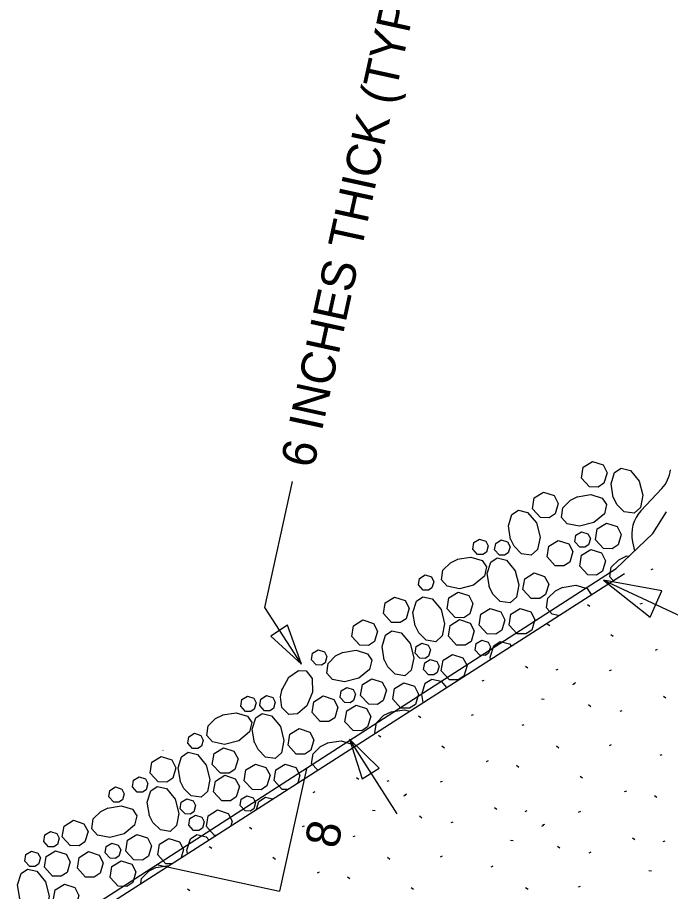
# Model space of a CAD drawing. Extents: x 2126110 to 2128246, y 1804858 to 1811658.
# Drawn here: x 2126563.9 to 2126659.7, y 1805428.3 to 1805556.7 of the extents above; entities that cross this region are included whole.
import ezdxf

# ---------------------------------------------------------------- set-up
doc = ezdxf.new("R2010")
doc.units = 0
doc.layers.add('1', color=7, linetype='Continuous')

msp = doc.modelspace()

# ---------------------------------------------------------------- linework, layer by layer
at = {"layer": '1'}
for p, q in [((2126600.2, 1805470.02), (2126604.25, 1805488.54)), ((2126653.13, 1805477.56), (2126653.52, 1805477.63)), ((2126573.8, 1805425.5), (2126651.74, 1805475.78)), ((2126574.76, 1805424.89), (2126652.95, 1805475.05)), ((2126656.88, 1805475.6), (2126657.18, 1805475.71)), ((2126649.91, 1805474.04), (2126706.07, 1805447.86)), ((2126605.54, 1805461.7), (2126600.2, 1805470.02)), ((2126647.89, 1805470.19), (2126647.53, 1805470.45)), ((2126655.29, 1805470.57), (2126655.59, 1805470.69)), ((2126641.99, 1805467.34), (2126641.64, 1805467.6)), ((2126651.33, 1805465.76), (2126650.98, 1805466.02)), ((2126657.53, 1805463.8), (2126657.83, 1805463.92)), ((2126638.77, 1805461.14), (2126638.42, 1805461.4)), ((2126642.93, 1805460.89), (2126643.23, 1805461.01)), ((2126650.78, 1805460.79), (2126651.08, 1805460.91)), ((2126632.08, 1805459.25), (2126632.38, 1805459.36)), ((2126645.38, 1805458.74), (2126645.68, 1805458.86)), ((2126645.52, 1805458.89), (2126645.82, 1805459.01)), ((2126659.04, 1805456.71), (2126658.68, 1805456.97)), ((2126640.79, 1805456.64), (2126641.19, 1805456.6)), ((2126648.04, 1805455.48), (2126647.69, 1805455.74)), ((2126630.49, 1805454.22), (2126630.79, 1805454.34)), ((2126652.34, 1805454.82), (2126652.64, 1805454.94)), ((2126623.08, 1805453.84), (2126622.73, 1805454.1)), ((2126637.93, 1805452.77), (2126638.22, 1805452.88)), ((2126619.62, 1805439.77), (2126612.6, 1805450.7)), ((2126617.19, 1805450.99), (2126616.84, 1805451.25)), ((2126626.53, 1805449.41), (2126626.18, 1805449.67)), ((2126643.35, 1805449.41), (2126642.99, 1805449.67)), ((2126650.75, 1805449.79), (2126651.05, 1805449.91)), ((2126585.26, 1805449.04), (2126585.23, 1805449.07)), ((2126658.19, 1805448.34), (2126658.49, 1805448.46)), ((2126632.73, 1805447.45), (2126633.03, 1805447.56)), ((2126637.45, 1805446.57), (2126637.1, 1805446.82)), ((2126606.27, 1805446.33), (2126602.35, 1805428.37)), ((2126613.97, 1805444.79), (2126613.62, 1805445.05)), ((2126618.13, 1805444.54), (2126618.42, 1805444.66)), ((2126625.97, 1805444.44), (2126626.27, 1805444.56)), ((2126646.79, 1805444.98), (2126646.44, 1805445.24)), ((2126603.48, 1805443.32), (2126602.74, 1805443.33)), ((2126607.28, 1805442.9), (2126607.57, 1805443.01)), ((2126652.99, 1805443.02), (2126653.29, 1805443.14)), ((2126620.58, 1805442.39), (2126620.88, 1805442.51)), ((2126620.72, 1805442.54), (2126621.02, 1805442.66)), ((2126657.71, 1805442.14), (2126657.36, 1805442.4)), ((2126615.99, 1805440.29), (2126616.39, 1805440.25)), ((2126634.23, 1805440.36), (2126633.88, 1805440.62)), ((2126638.39, 1805440.11), (2126638.69, 1805440.23)), ((2126623.24, 1805439.13), (2126622.88, 1805439.39)), ((2126646.24, 1805440.01), (2126646.54, 1805440.13)), ((2126598.28, 1805437.49), (2126597.93, 1805437.75)), ((2126605.69, 1805437.87), (2126605.98, 1805437.99)), ((2126627.54, 1805438.47), (2126627.84, 1805438.58)), ((2126640.84, 1805437.96), (2126641.14, 1805438.08)), ((2126640.98, 1805438.11), (2126641.28, 1805438.23)), ((2126592.98, 1805436.58), (2126592.8, 1805436.58)), ((2126613.12, 1805436.42), (2126613.42, 1805436.53)), ((2126636.25, 1805435.86), (2126636.65, 1805435.82)), ((2126654.5, 1805435.93), (2126654.14, 1805436.19)), ((2126658.65, 1805435.69), (2126658.95, 1805435.8)), ((2126592.39, 1805434.64), (2126592.03, 1805434.9)), ((2126643.5, 1805434.7), (2126643.15, 1805434.96)), ((2126647.8, 1805434.04), (2126648.1, 1805434.16)), ((2126601.73, 1805433.06), (2126601.37, 1805433.32)), ((2126618.54, 1805433.06), (2126618.19, 1805433.32)), ((2126625.95, 1805433.44), (2126626.25, 1805433.56)), ((2126584.18, 1805431.86), (2126586.12, 1805432.18)), ((2126584.3, 1805432.32), (2126602.35, 1805428.37)), ((2126586.46, 1805432.4), (2126585.66, 1805432.42)), ((2126607.93, 1805431.1), (2126608.22, 1805431.21)), ((2126633.39, 1805431.99), (2126633.68, 1805432.11)), ((2126656.52, 1805431.43), (2126656.92, 1805431.39)), ((2126612.65, 1805430.21), (2126612.3, 1805430.47)), ((2126589.17, 1805428.44), (2126588.81, 1805428.7)), ((2126621.99, 1805428.63), (2126621.64, 1805428.89)), ((2126638.81, 1805428.63), (2126638.45, 1805428.89)), ((2126646.21, 1805429.02), (2126646.51, 1805429.13))]:
    msp.add_line(p, q, dxfattribs=at)
for points in [[(2126647.82, 1805487.76), (2126646.64, 1805489.05), (2126646.89, 1805490.64), (2126648.26, 1805491.49), (2126649.82, 1805490.98), (2126650.41, 1805489.83), (2126649.96, 1805488.3), (2126649.09, 1805487.73), (2126647.82, 1805487.76)], [(2126651.33, 1805486.19), (2126651, 1805488.19), (2126651.52, 1805489.86), (2126652.46, 1805490.49), (2126653.83, 1805490.17), (2126655.12, 1805488.61), (2126655.65, 1805486.51), (2126655.3, 1805484.73), (2126654.37, 1805483.88), (2126652.93, 1805484.1), (2126651.84, 1805485.18), (2126651.3, 1805486.28)], [(2126640.66, 1805483.25), (2126639.47, 1805484.54), (2126639.72, 1805486.13), (2126641.1, 1805486.98), (2126642.65, 1805486.48), (2126643.25, 1805485.33), (2126642.79, 1805483.8), (2126641.93, 1805483.22), (2126640.66, 1805483.25)], [(2126646.04, 1805486.29), (2126648.04, 1805486.62), (2126649.7, 1805486.1), (2126650.34, 1805485.16), (2126650.02, 1805483.79), (2126648.45, 1805482.5), (2126646.36, 1805481.97), (2126644.57, 1805482.33), (2126643.73, 1805483.26), (2126643.94, 1805484.69), (2126645.03, 1805485.78), (2126646.13, 1805486.32)], [(2126655.38, 1805484.22), (2126658.45, 1805487.53)], [(2126636.26, 1805480.04), (2126635.93, 1805482.04), (2126636.45, 1805483.7), (2126637.39, 1805484.34), (2126638.75, 1805484.01), (2126640.05, 1805482.45), (2126640.58, 1805480.36), (2126640.22, 1805478.57), (2126639.29, 1805477.73), (2126637.86, 1805477.94), (2126636.77, 1805479.03), (2126636.23, 1805480.12)], [(2126651.74, 1805475.78), (2126657.13, 1805480.92), (2126659.15, 1805484.08)], [(2126649.9, 1805478.68), (2126648.71, 1805479.98), (2126648.97, 1805481.57), (2126650.34, 1805482.41), (2126651.89, 1805481.91), (2126652.49, 1805480.76), (2126652.04, 1805479.23), (2126651.17, 1805478.66), (2126649.9, 1805478.69)], [(2126631.41, 1805477.83), (2126630.7, 1805478.61), (2126630.85, 1805479.56), (2126631.67, 1805480.07), (2126632.61, 1805479.77), (2126632.96, 1805479.08), (2126632.69, 1805478.16), (2126632.17, 1805477.82), (2126631.41, 1805477.83)], [(2126646.4, 1805478.92), (2126645.69, 1805479.7), (2126645.84, 1805480.65), (2126646.67, 1805481.16), (2126647.6, 1805480.86), (2126647.96, 1805480.17), (2126647.69, 1805479.25), (2126647.16, 1805478.91), (2126646.4, 1805478.92)], [(2126634.62, 1805477.72), (2126633.91, 1805478.5), (2126634.06, 1805479.45), (2126634.88, 1805479.96), (2126635.82, 1805479.66), (2126636.17, 1805478.97), (2126635.9, 1805478.05), (2126635.38, 1805477.7), (2126634.62, 1805477.72)], [(2126642.79, 1805476.16), (2126641.61, 1805477.46), (2126641.86, 1805479.05), (2126643.23, 1805479.89), (2126644.79, 1805479.39), (2126645.38, 1805478.24), (2126644.93, 1805476.71), (2126644.06, 1805476.14), (2126642.79, 1805476.17)], [(2126654.47, 1805478.38), (2126654.17, 1805479.7)], [(2126628.42, 1805477.12), (2126630.42, 1805477.45), (2126632.09, 1805476.93), (2126632.72, 1805475.99), (2126632.4, 1805474.62), (2126630.83, 1805473.33), (2126628.74, 1805472.8), (2126626.96, 1805473.15), (2126626.11, 1805474.08), (2126626.32, 1805475.52), (2126627.41, 1805476.61), (2126628.51, 1805477.15)], [(2126647.6, 1805474.83), (2126646.41, 1805476.12), (2126646.67, 1805477.71), (2126648.04, 1805478.56), (2126649.59, 1805478.05), (2126650.19, 1805476.9), (2126649.74, 1805475.37), (2126648.87, 1805474.8), (2126647.6, 1805474.83)], [(2126651.3, 1805473.99), (2126650.81, 1805474.53), (2126651.03, 1805475.96), (2126652.12, 1805477.05), (2126653.21, 1805477.59)], [(2126633.14, 1805473.03), (2126632.81, 1805475.03), (2126633.33, 1805476.69), (2126634.27, 1805477.33), (2126635.64, 1805477), (2126636.93, 1805475.44), (2126637.46, 1805473.35), (2126637.11, 1805471.56), (2126636.18, 1805470.72), (2126634.74, 1805470.93), (2126633.65, 1805472.02), (2126633.11, 1805473.11)], [(2126639.25, 1805471.38), (2126638.06, 1805472.67), (2126638.32, 1805474.26), (2126639.69, 1805475.11), (2126641.24, 1805474.6), (2126641.84, 1805473.46), (2126641.39, 1805471.93), (2126640.52, 1805471.35), (2126639.25, 1805471.38)], [(2126623.43, 1805472.58), (2126622.72, 1805473.36), (2126622.87, 1805474.31), (2126623.69, 1805474.82), (2126624.63, 1805474.52), (2126624.98, 1805473.83), (2126624.71, 1805472.91), (2126624.19, 1805472.57), (2126623.43, 1805472.58)], [(2126628.13, 1805468.57), (2126626.94, 1805469.86), (2126627.19, 1805471.46), (2126628.57, 1805472.3), (2126630.12, 1805471.8), (2126630.72, 1805470.65), (2126630.27, 1805469.12), (2126629.4, 1805468.54), (2126628.13, 1805468.57)], [(2126643.3, 1805468.85), (2126642.36, 1805469.04), (2126641.51, 1805469.97), (2126641.73, 1805471.41), (2126642.82, 1805472.5), (2126643.91, 1805473.04)], [(2126643.82, 1805473), (2126645.83, 1805473.33), (2126647.49, 1805472.82), (2126648.09, 1805471.93)], [(2126618.78, 1805467.85), (2126617.59, 1805469.14), (2126617.85, 1805470.74), (2126619.22, 1805471.58), (2126620.78, 1805471.08), (2126621.37, 1805469.93), (2126620.92, 1805468.4), (2126620.05, 1805467.82), (2126618.78, 1805467.85)], [(2126622.25, 1805467.33), (2126621.92, 1805469.33), (2126622.44, 1805470.99), (2126623.38, 1805471.63), (2126624.75, 1805471.3), (2126626.04, 1805469.74), (2126626.57, 1805467.65), (2126626.22, 1805465.86), (2126625.29, 1805465.01), (2126623.85, 1805465.23), (2126622.76, 1805466.32), (2126622.22, 1805467.41)], [(2126632.82, 1805466.17), (2126631.63, 1805467.46), (2126631.88, 1805469.06), (2126633.26, 1805469.9), (2126634.81, 1805469.4), (2126635.41, 1805468.25), (2126634.95, 1805466.72), (2126634.09, 1805466.14), (2126632.82, 1805466.17)], [(2126637.21, 1805466.18), (2126636.03, 1805467.47), (2126636.28, 1805469.07), (2126637.65, 1805469.91), (2126639.21, 1805469.41), (2126639.8, 1805468.26), (2126639.35, 1805466.73), (2126638.48, 1805466.15), (2126637.21, 1805466.18)], [(2126614.13, 1805464.49), (2126612.94, 1805465.78), (2126613.19, 1805467.37), (2126614.57, 1805468.22), (2126616.12, 1805467.71), (2126616.72, 1805466.56), (2126616.26, 1805465.04), (2126615.4, 1805464.46), (2126614.13, 1805464.49)], [(2126628.32, 1805464.53), (2126627.13, 1805465.82), (2126627.39, 1805467.41), (2126628.76, 1805468.26), (2126630.31, 1805467.75), (2126630.91, 1805466.6), (2126630.46, 1805465.07), (2126629.59, 1805464.5), (2126628.32, 1805464.53)], [(2126617.71, 1805462.33), (2126617.38, 1805464.33), (2126617.9, 1805465.99), (2126618.84, 1805466.63), (2126620.21, 1805466.3), (2126621.5, 1805464.74), (2126622.03, 1805462.65), (2126621.67, 1805460.86), (2126620.74, 1805460.02), (2126619.31, 1805460.23), (2126618.22, 1805461.32), (2126617.68, 1805462.41)], [(2126622.94, 1805462.58), (2126622.22, 1805463.35), (2126622.38, 1805464.31), (2126623.2, 1805464.81), (2126624.13, 1805464.51), (2126624.49, 1805463.82), (2126624.22, 1805462.9), (2126623.7, 1805462.56), (2126622.94, 1805462.58)], [(2126631.75, 1805463.02), (2126631.04, 1805463.8), (2126631.19, 1805464.75), (2126632.01, 1805465.26), (2126632.94, 1805464.96), (2126633.3, 1805464.27), (2126633.03, 1805463.35), (2126632.51, 1805463), (2126631.75, 1805463.02)], [(2126633.32, 1805462.45), (2126633.27, 1805462.73), (2126633.79, 1805464.39), (2126634.73, 1805465.03), (2126636.1, 1805464.7), (2126636.35, 1805464.4)], [(2126607.73, 1805461.61), (2126607.02, 1805462.38), (2126607.17, 1805463.34), (2126607.99, 1805463.84), (2126608.92, 1805463.54), (2126609.28, 1805462.85), (2126609.01, 1805461.93), (2126608.49, 1805461.59), (2126607.73, 1805461.61)], [(2126611.57, 1805463.44), (2126613.57, 1805463.77), (2126615.23, 1805463.25), (2126615.87, 1805462.31), (2126615.55, 1805460.94), (2126613.98, 1805459.65), (2126611.89, 1805459.12), (2126610.1, 1805459.48), (2126609.26, 1805460.41), (2126609.47, 1805461.84), (2126610.56, 1805462.93), (2126611.66, 1805463.47)], [(2126624.2, 1805460.17), (2126623.49, 1805460.94), (2126623.64, 1805461.9), (2126624.47, 1805462.41), (2126625.4, 1805462.1), (2126625.76, 1805461.42), (2126625.48, 1805460.5), (2126624.96, 1805460.15), (2126624.2, 1805460.17)], [(2126627.27, 1805459.43), (2126626.08, 1805460.72), (2126626.33, 1805462.32), (2126627.71, 1805463.16), (2126629.26, 1805462.66), (2126629.86, 1805461.51), (2126629.41, 1805459.98), (2126628.54, 1805459.4), (2126627.27, 1805459.43)], [(2126602.72, 1805458.02), (2126603.68, 1805459.8), (2126605.11, 1805460.79), (2126606.24, 1805460.72), (2126607.13, 1805459.62), (2126607.19, 1805457.6), (2126606.33, 1805455.62), (2126604.95, 1805454.43), (2126603.7, 1805454.33), (2126602.69, 1805455.38), (2126602.5, 1805456.91), (2126602.74, 1805458.1)], [(2126615.43, 1805455.84), (2126614.24, 1805457.13), (2126614.5, 1805458.72), (2126615.87, 1805459.57), (2126617.42, 1805459.06), (2126618.02, 1805457.91), (2126617.57, 1805456.38), (2126616.7, 1805455.81), (2126615.43, 1805455.84)], [(2126623.4, 1805456.09), (2126623.22, 1805457.25), (2126623.73, 1805458.91), (2126624.67, 1805459.54), (2126626.04, 1805459.22), (2126626.82, 1805458.28)], [(2126611.93, 1805456.07), (2126611.22, 1805456.85), (2126611.37, 1805457.8), (2126612.2, 1805458.31), (2126613.13, 1805458.01), (2126613.49, 1805457.32), (2126613.21, 1805456.4), (2126612.69, 1805456.06), (2126611.93, 1805456.07)], [(2126620.13, 1805455.27), (2126618.95, 1805456.56), (2126619.2, 1805458.15), (2126620.58, 1805459), (2126622.13, 1805458.49), (2126622.72, 1805457.34), (2126622.27, 1805455.81), (2126621.41, 1805455.24), (2126620.13, 1805455.27)], [(2126597.35, 1805454.78), (2126596.64, 1805455.55), (2126596.79, 1805456.51), (2126597.61, 1805457.02), (2126598.55, 1805456.71), (2126598.9, 1805456.03), (2126598.63, 1805455.11), (2126598.11, 1805454.76), (2126597.35, 1805454.78)], [(2126600.15, 1805454.87), (2126599.44, 1805455.65), (2126599.59, 1805456.6), (2126600.41, 1805457.11), (2126601.35, 1805456.81), (2126601.7, 1805456.12), (2126601.43, 1805455.2), (2126600.91, 1805454.86), (2126600.15, 1805454.87)], [(2126608.32, 1805453.32), (2126607.13, 1805454.61), (2126607.39, 1805456.2), (2126608.76, 1805457.05), (2126610.32, 1805456.54), (2126610.91, 1805455.39), (2126610.46, 1805453.86), (2126609.59, 1805453.29), (2126608.32, 1805453.32)], [(2126613.13, 1805451.98), (2126611.94, 1805453.27), (2126612.19, 1805454.86), (2126613.57, 1805455.71), (2126615.12, 1805455.2), (2126615.72, 1805454.05), (2126615.27, 1805452.52), (2126614.4, 1805451.95), (2126613.13, 1805451.98)], [(2126593.95, 1805454.27), (2126595.95, 1805454.6), (2126597.61, 1805454.08), (2126598.25, 1805453.14), (2126597.93, 1805451.77), (2126596.36, 1805450.48), (2126594.27, 1805449.95), (2126592.49, 1805450.31), (2126591.64, 1805451.24), (2126591.85, 1805452.67), (2126592.94, 1805453.76), (2126594.04, 1805454.3)], [(2126598.67, 1805450.18), (2126598.34, 1805452.18), (2126598.86, 1805453.84), (2126599.8, 1805454.48), (2126601.17, 1805454.15), (2126602.46, 1805452.59), (2126602.99, 1805450.5), (2126602.63, 1805448.71), (2126601.7, 1805447.87), (2126600.27, 1805448.08), (2126599.18, 1805449.17), (2126598.64, 1805450.26)], [(2126616.41, 1805451.61), (2126616.34, 1805451.68), (2126616.56, 1805453.12), (2126617.65, 1805454.21), (2126618.74, 1805454.74)], [(2126618.65, 1805454.71), (2126620.66, 1805455.04), (2126621.4, 1805454.81)], [(2126604.78, 1805448.53), (2126603.59, 1805449.82), (2126603.85, 1805451.42), (2126605.22, 1805452.26), (2126606.77, 1805451.76), (2126607.37, 1805450.61), (2126606.92, 1805449.08), (2126606.05, 1805448.5), (2126604.78, 1805448.53)], [(2126589.58, 1805449.34), (2126588.86, 1805450.11), (2126589.02, 1805451.07), (2126589.84, 1805451.57), (2126590.77, 1805451.27), (2126591.13, 1805450.58), (2126590.86, 1805449.67), (2126590.34, 1805449.32), (2126589.58, 1805449.34)], [(2126609.35, 1805450.16), (2126611.36, 1805450.48), (2126613.02, 1805449.97), (2126613.27, 1805449.59)], [(2126593.66, 1805445.72), (2126592.47, 1805447.01), (2126592.72, 1805448.61), (2126594.1, 1805449.45), (2126595.65, 1805448.95), (2126596.25, 1805447.8), (2126595.79, 1805446.27), (2126594.93, 1805445.7), (2126593.66, 1805445.72)], [(2126607.95, 1805446.18), (2126607.89, 1805446.19), (2126607.04, 1805447.12), (2126607.26, 1805448.56), (2126608.35, 1805449.65), (2126609.44, 1805450.19)], [(2126584.52, 1805444.44), (2126583.33, 1805445.73), (2126583.59, 1805447.33), (2126584.96, 1805448.17), (2126586.51, 1805447.67), (2126587.11, 1805446.52), (2126586.66, 1805444.99), (2126585.79, 1805444.41), (2126584.52, 1805444.44)], [(2126587.78, 1805444.48), (2126587.45, 1805446.48), (2126587.97, 1805448.14), (2126588.91, 1805448.78), (2126590.28, 1805448.45), (2126591.57, 1805446.89), (2126592.1, 1805444.8), (2126591.75, 1805443.01), (2126590.81, 1805442.17), (2126589.38, 1805442.38), (2126588.29, 1805443.47), (2126587.75, 1805444.56)], [(2126598.35, 1805443.32), (2126597.16, 1805444.61), (2126597.41, 1805446.21), (2126598.79, 1805447.05), (2126600.34, 1805446.55), (2126600.94, 1805445.4), (2126600.48, 1805443.87), (2126599.62, 1805443.29), (2126598.35, 1805443.32)], [(2126602.74, 1805443.33), (2126601.56, 1805444.62), (2126601.81, 1805446.22), (2126603.18, 1805447.06), (2126604.74, 1805446.56), (2126605.33, 1805445.41), (2126605, 1805444.29)], [(2126593.85, 1805441.68), (2126592.66, 1805442.97), (2126592.92, 1805444.56), (2126594.29, 1805445.41), (2126595.84, 1805444.9), (2126596.44, 1805443.75), (2126595.99, 1805442.23), (2126595.12, 1805441.65), (2126593.85, 1805441.68)], [(2126581.45, 1805442.94), (2126580.74, 1805443.72), (2126580.89, 1805444.67), (2126581.72, 1805445.18), (2126582.65, 1805444.88), (2126583.01, 1805444.19), (2126582.74, 1805443.27), (2126582.22, 1805442.93), (2126581.45, 1805442.94)], [(2126578, 1805441.46), (2126577.29, 1805442.23), (2126577.44, 1805443.19), (2126578.26, 1805443.7), (2126579.2, 1805443.39), (2126579.55, 1805442.7), (2126579.28, 1805441.79), (2126578.76, 1805441.44), (2126578, 1805441.46)], [(2126583.24, 1805439.48), (2126582.91, 1805441.48), (2126583.43, 1805443.14), (2126584.37, 1805443.78), (2126585.74, 1805443.46), (2126587.03, 1805441.89), (2126587.56, 1805439.8), (2126587.2, 1805438.01), (2126586.27, 1805437.17), (2126584.84, 1805437.38), (2126583.75, 1805438.47), (2126583.21, 1805439.56)], [(2126588.47, 1805439.73), (2126587.75, 1805440.5), (2126587.91, 1805441.46), (2126588.73, 1805441.97), (2126589.66, 1805441.66), (2126590.02, 1805440.97), (2126589.75, 1805440.06), (2126589.23, 1805439.71), (2126588.47, 1805439.73)], [(2126597.28, 1805440.17), (2126596.57, 1805440.95), (2126596.72, 1805441.9), (2126597.54, 1805442.41), (2126598.47, 1805442.11), (2126598.83, 1805441.42), (2126598.56, 1805440.5), (2126598.04, 1805440.16), (2126597.28, 1805440.17)], [(2126598.97, 1805440.42), (2126599.32, 1805441.54), (2126600.26, 1805442.18), (2126601.32, 1805441.93)], [(2126577.1, 1805440.59), (2126579.1, 1805440.92), (2126580.76, 1805440.41), (2126581.4, 1805439.46), (2126581.07, 1805438.1), (2126579.51, 1805436.8), (2126577.42, 1805436.27), (2126575.63, 1805436.63), (2126574.79, 1805437.56), (2126575, 1805439), (2126576.09, 1805440.09), (2126577.18, 1805440.62)], [(2126592.8, 1805436.58), (2126591.61, 1805437.87), (2126591.86, 1805439.47), (2126593.24, 1805440.31), (2126594.79, 1805439.81), (2126595.39, 1805438.66), (2126595.19, 1805438)], [(2126589.73, 1805437.32), (2126589.02, 1805438.1), (2126589.17, 1805439.05), (2126589.99, 1805439.56), (2126590.93, 1805439.26), (2126591.29, 1805438.57), (2126591.01, 1805437.65), (2126590.49, 1805437.3), (2126589.73, 1805437.32)], [(2126571.64, 1805435.07), (2126570.45, 1805436.37), (2126570.71, 1805437.96), (2126572.08, 1805438.8), (2126573.63, 1805438.3), (2126574.23, 1805437.15), (2126573.78, 1805435.62), (2126572.91, 1805435.05), (2126571.64, 1805435.08)], [(2126568.44, 1805434.91), (2126567.73, 1805435.69), (2126567.89, 1805436.64), (2126568.71, 1805437.15), (2126569.64, 1805436.85), (2126570, 1805436.16), (2126569.73, 1805435.24), (2126569.21, 1805434.89), (2126568.44, 1805434.91)], [(2126580.96, 1805432.99), (2126579.77, 1805434.28), (2126580.03, 1805435.87), (2126581.4, 1805436.72), (2126582.95, 1805436.21), (2126583.55, 1805435.06), (2126583.1, 1805433.54), (2126582.23, 1805432.96), (2126580.96, 1805432.99)], [(2126588.82, 1805433.92), (2126588.75, 1805434.4), (2126589.26, 1805436.06), (2126590.2, 1805436.7), (2126591.57, 1805436.37), (2126591.95, 1805435.92)], [(2126577.46, 1805433.23), (2126576.75, 1805434), (2126576.9, 1805434.96), (2126577.73, 1805435.46), (2126578.66, 1805435.16), (2126579.02, 1805434.47), (2126578.74, 1805433.55), (2126578.22, 1805433.21), (2126577.46, 1805433.23)], [(2126585.66, 1805432.42), (2126584.48, 1805433.71), (2126584.73, 1805435.3), (2126586.1, 1805436.15), (2126587.66, 1805435.64), (2126588.25, 1805434.49), (2126587.91, 1805433.33)], [(2126565.68, 1805432.03), (2126564.97, 1805432.8), (2126565.12, 1805433.76), (2126565.94, 1805434.26), (2126566.88, 1805433.96), (2126567.23, 1805433.27), (2126566.96, 1805432.35), (2126566.44, 1805432.01), (2126565.68, 1805432.03)], [(2126569.03, 1805430.6), (2126567.84, 1805431.9), (2126568.09, 1805433.49), (2126569.47, 1805434.33), (2126571.02, 1805433.83), (2126571.62, 1805432.68), (2126571.17, 1805431.15), (2126570.3, 1805430.58), (2126569.03, 1805430.61)], [(2126573.85, 1805430.47), (2126572.66, 1805431.76), (2126572.92, 1805433.35), (2126574.29, 1805434.2), (2126575.84, 1805433.69), (2126576.44, 1805432.54), (2126575.99, 1805431.02), (2126575.12, 1805430.44), (2126573.85, 1805430.47)], [(2126578.66, 1805429.13), (2126577.47, 1805430.42), (2126577.72, 1805432.01), (2126579.1, 1805432.86), (2126580.65, 1805432.35), (2126581.25, 1805431.21), (2126580.79, 1805429.68), (2126579.93, 1805429.1), (2126578.66, 1805429.13)], [(2126564.2, 1805427.33), (2126563.87, 1805429.33), (2126564.39, 1805430.99), (2126565.33, 1805431.63), (2126566.7, 1805431.31), (2126567.99, 1805429.74), (2126568.52, 1805427.65), (2126568.16, 1805425.86), (2126567.23, 1805425.02), (2126565.8, 1805425.23), (2126564.71, 1805426.32), (2126564.17, 1805427.42)], [(2126581.98, 1805429.52), (2126582.09, 1805430.27), (2126583.18, 1805431.36), (2126584.27, 1805431.9)], [(2126570.31, 1805425.68), (2126569.12, 1805426.97), (2126569.38, 1805428.57), (2126570.75, 1805429.41), (2126572.3, 1805428.91), (2126572.9, 1805427.76), (2126572.45, 1805426.23), (2126571.58, 1805425.66), (2126570.31, 1805425.68)]]:
    msp.add_lwpolyline(points, dxfattribs=at)
for points in [[(2126658.46, 1805472.47), (2126649.91, 1805474.04), (2126656.72, 1805468.63)], [(2126601.05, 1805465.81), (2126605.54, 1805461.7), (2126603.52, 1805467.44)], [(2126616.97, 1805446.46), (2126612.6, 1805450.7), (2126614.47, 1805444.9)]]:
    msp.add_lwpolyline(points, close=True, dxfattribs=at)
for centre, start, end in [((2126654.77, 1805490.91), 317.1258, 352.6464), ((2126659.04, 1805480.82), 137.1258, 192.8899)]:
    msp.add_arc(centre, 5, start, end, dxfattribs=at)

# ---------------------------------------------------------------- texts
for s, p in [('6 INCHES THICK (TYP.)', (2126607.34, 1805490.34)), ('8', (2126610.85, 1805434.47))]:
    msp.add_text(s, height=5, rotation=77.6736, dxfattribs=at).set_placement(p)

doc.saveas('drawing.dxf')
